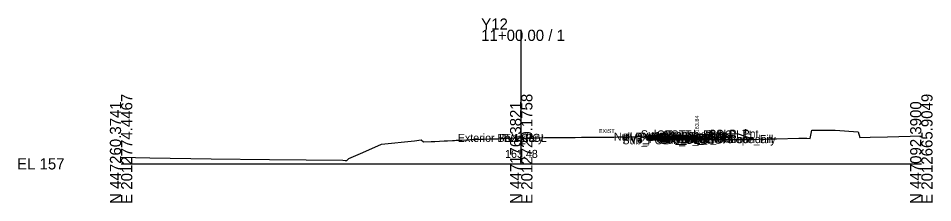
# Model space of a CAD drawing. Extents: x -26 to 1203, y -10 to 9542.
# Drawn here: x -25.7 to 202.8, y 1990.3 to 2036.3 of the extents above; entities that cross this region are included whole.
import ezdxf

# ---------------------------------------------------------------- set-up
doc = ezdxf.new("R2010")
doc.units = 0
for name, color, linetype in [('Default', 7, 'Continuous'), ('Exist Cross Section Cell', 7, 'Continuous'), ('Exist XS Center Line Elevation Label', 7, 'Continuous'), ('Exist XS Ground Line', 7, 'Continuous'), ('Prop CMT Conc Surface', 7, 'Continuous'), ('Prop CMT Concrete Structures', 7, 'Continuous'), ('Prop CMT Pvmt Course 1', 7, 'Continuous'), ('Prop CMT Pvmt Course 1 CG', 7, 'Continuous'), ('Prop CMT Pvmt Course 2', 7, 'Continuous'), ('Prop CMT Pvmt Course 3', 7, 'Continuous'), ('Prop CMT Pvmt Surface', 7, 'Continuous'), ('Prop CMT Slope Grass', 7, 'Continuous'), ('Prop CMT Subgrade Earthwork', 7, 'Continuous'), ('Prop XS Earthwork Shape', 7, 'Continuous'), ('Prop XS Hydro Elevations', 7, 'Continuous'), ('Prop XS SE Text', 7, 'Continuous'), ('Prop XS Side Slope Text', 7, 'Continuous'), ('Scratch_Level_0', 7, 'Continuous')]:
    doc.layers.add(name, color=color, linetype=linetype)

msp = doc.modelspace()

# ---------------------------------------------------------------- linework, layer by layer
at = {"layer": 'Exist Cross Section Cell'}
for p, q in [((100, 2000), (100, 2033.47)), ((0, 2000), (100, 2000)), ((100, 2000), (200, 2000))]:
    msp.add_line(p, q, dxfattribs=at)
at = {"layer": 'Exist XS Ground Line'}
msp.add_lwpolyline([(0, 2001.63), (7.18, 2001.5), (22.54, 2001.22), (37.11, 2001.06), (55.38, 2000.92), (56.03, 2000.85), (56.38, 2000.81), (56.88, 2001.31), (60.43, 2002.79), (65.08, 2004.91), (73.35, 2005.77), (75, 2005.97), (75.54, 2005.5), (77.46, 2005.55), (78.38, 2005.59), (80.74, 2005.72), (81.55, 2005.77), (82.8, 2005.83), (83.36, 2005.86), (83.72, 2005.87), (85.17, 2005.94), (86.69, 2006.02), (87.35, 2006.05), (87.97, 2006.07), (88.66, 2006.09), (89.66, 2006.12), (90.57, 2006.15), (91.96, 2006.2), (92.63, 2006.23), (94.18, 2006.28), (95.61, 2006.33), (96.58, 2006.37), (98.26, 2006.45), (98.61, 2006.46), (98.94, 2006.17), (99.54, 2006.47), (100, 2006.48), (100.44, 2006.5), (101.04, 2006.2), (101.37, 2006.47), (101.74, 2006.47), (102.35, 2006.48), (104.57, 2006.52), (105.83, 2006.54), (107.54, 2006.58), (108.68, 2006.6), (110.78, 2006.61), (111.35, 2006.61), (113.49, 2006.61), (115.04, 2006.62), (116.46, 2006.62), (119.04, 2006.64), (119.59, 2006.64), (121.13, 2006.66), (122.39, 2006.67), (123.11, 2006.68), (124.22, 2006.7), (124.93, 2006.71), (125.37, 2006.71), (127.46, 2006.74), (128.34, 2006.75), (128.82, 2006.76), (130.95, 2006.8), (131.48, 2006.79), (133.42, 2006.94), (134, 2007.44), (138.17, 2007.26), (139.33, 2007.22), (142.95, 2006.78), (144.41, 2006.55), (148.38, 2005.87), (149.45, 2005.96), (152.83, 2006.02), (159.34, 2006.19), (162.22, 2006.21), (163.82, 2006.23), (169.37, 2006.37), (171.34, 2006.37), (172.25, 2006.36), (172.65, 2008.39), (174.53, 2008.39), (178.5, 2008.39), (184.25, 2007.98), (184.61, 2006.58), (187.18, 2006.68), (191.57, 2006.77), (200, 2007)], dxfattribs=at)
at = {"layer": 'Prop CMT Conc Surface'}
msp.add_lwpolyline([(141.94, 2006.9), (143.94, 2006.84), (143.95, 2007.34), (144.45, 2007.34)], dxfattribs=at)
at = {"layer": 'Prop CMT Concrete Structures'}
for points in [[(141.94, 2006.9), (143.94, 2006.84), (143.95, 2007.34), (144.45, 2007.34)], [(144.45, 2007.34), (144.44, 2006.34), (141.94, 2006.32)], [(141.94, 2006.32), (141.94, 2006.9)]]:
    msp.add_lwpolyline(points, dxfattribs=at)
at = {"layer": 'Prop CMT Pvmt Course 1'}
for points in [[(131.46, 2006.79), (141.94, 2006.9)], [(131.46, 2006.79), (131.46, 2006.79)], [(131.46, 2006.54), (131.46, 2006.79)], [(141.94, 2006.65), (131.46, 2006.54)], [(141.94, 2006.9), (141.94, 2006.65)], [(100, 2006.48), (100, 2006.48)]]:
    msp.add_lwpolyline(points, dxfattribs=at)
at = {"layer": 'Prop CMT Pvmt Course 1 CG'}
for points in [[(141.94, 2006.32), (144.94, 2006.35), (145.27, 2006.02)], [(141.94, 2005.98), (141.94, 2006.32)], [(145.27, 2006.02), (141.94, 2005.98)]]:
    msp.add_lwpolyline(points, dxfattribs=at)
at = {"layer": 'Prop CMT Pvmt Course 2'}
for points in [[(131.46, 2006.54), (141.94, 2006.65)], [(131.46, 2006.21), (131.46, 2006.54)], [(141.94, 2006.65), (141.94, 2006.32)], [(141.94, 2006.32), (131.46, 2006.21)]]:
    msp.add_lwpolyline(points, dxfattribs=at)
at = {"layer": 'Prop CMT Pvmt Course 3'}
for points in [[(131.46, 2006.21), (141.94, 2006.32)], [(131.46, 2005.88), (131.46, 2006.21)], [(141.94, 2005.98), (131.46, 2005.88)], [(141.94, 2006.32), (141.94, 2005.98)]]:
    msp.add_lwpolyline(points, dxfattribs=at)
at = {"layer": 'Prop CMT Pvmt Surface'}
msp.add_lwpolyline([(131.46, 2006.79), (141.94, 2006.9)], dxfattribs=at)
at = {"layer": 'Prop CMT Slope Grass'}
msp.add_lwpolyline([(144.45, 2007.34), (153.95, 2007.53), (158.06, 2006.16)], dxfattribs=at)
at = {"layer": 'Prop CMT Subgrade Earthwork'}
for points in [[(131.46, 2005.88), (131.46, 2006.79)], [(141.94, 2005.98), (145.27, 2006.02), (146.64, 2007.38)], [(131.46, 2005.88), (141.94, 2005.98)], [(141.94, 2005.98), (131.46, 2005.88)]]:
    msp.add_lwpolyline(points, dxfattribs=at)
at = {"layer": 'Prop XS Earthwork Shape'}
for points in [[(131.46, 2005.88), (131.46, 2006.79), (131.48, 2006.79), (131.5, 2006.79), (141.94, 2006.9), (141.94, 2006.32), (144.44, 2006.34), (144.44, 2006.54), (145.6, 2006.35), (145.27, 2006.02), (141.94, 2005.98)], [(139.33, 2007.22), (141.94, 2006.9), (131.5, 2006.79), (133.42, 2006.94), (134, 2007.44), (138.17, 2007.26)], [(141.94, 2006.32), (141.94, 2006.9), (141.99, 2006.9), (142.95, 2006.78), (144.41, 2006.55), (144.44, 2006.54), (144.44, 2006.34)], [(153.95, 2007.53), (158.06, 2006.16), (152.83, 2006.02), (149.45, 2005.96), (148.38, 2005.87), (145.6, 2006.35), (146.64, 2007.38)]]:
    msp.add_lwpolyline(points, close=True, dxfattribs=at)

# ---------------------------------------------------------------- texts
at = {"layer": 'Default'}
msp.add_text('-', height=0.0001, dxfattribs=at).set_placement((0, 2000))
at = {"layer": 'Exist Cross Section Cell'}
for s, p in [('Y12', (90, 2033.47)), ('11+00.00 / 1', (90, 2030.67)), ('EL 157', (-26, 1998.6))]:
    msp.add_text(s, height=2.8, dxfattribs=at).set_placement(p)
for s, p in [('E 2012774.4467', (2.8, 1990)), ('E 2012720.1758', (102.8, 1990)), ('E 2012665.9049', (202.8, 1990)), ('N 447260.3741', (0, 1990)), ('N 447176.3821', (100, 1990)), ('N 447092.3900', (200, 1990))]:
    msp.add_text(s, height=2.8, rotation=90, dxfattribs=at).set_placement(p)
at = {"layer": 'Exist XS Center Line Elevation Label'}
msp.add_text('163.48', height=2, dxfattribs=at).set_placement((95.96, 2001.48))
at = {"layer": 'Prop XS Hydro Elevations'}
msp.add_text('163.84', height=1, rotation=90, dxfattribs=at).set_placement((144.44, 2007.84))
at = {"layer": 'Prop XS SE Text'}
msp.add_text('EXIST', height=1, rotation=0.5724, dxfattribs=at).set_placement((119.39, 2007.67))
at = {"layer": 'Prop XS Side Slope Text'}
msp.add_text('3:1', height=1, rotation=341.5651, dxfattribs=at).set_placement((155.49, 2007.81))
at = {"layer": 'Scratch_Level_0'}
for s, p in [('Exterior Boundary', (84.14, 2005.48)), ('PV1_PGL', (94.47, 2005.48)), ('EX CL', (95.67, 2005.48)), ('Null Ex EOP', (123.17, 2005.79)), ('Sub_PGL', (125.28, 2004.88)), ('PV2_PGL', (125.37, 2005.54)), ('PV3_PGL', (125.37, 2005.21)), ('PV1', (129.54, 2005.79)), ('Sub_Trench_Out_DLT', (129.9, 2006.38)), ('CG_Top_Face', (133.9, 2006.34)), ('CG1_Shelf_Out', (134.19, 2005.35)), ('CG_Bot_IE', (134.55, 2005.32)), ('Sub_OEOT', (134.72, 2004.98)), ('CG_Top_Gut', (134.87, 2005.84)), ('PV2_OEOT', (134.81, 2005.65)), ('PV3_OEOT', (134.81, 2005.32)), ('CG_Top_BOC', (135.42, 2006.34)), ('CG_Bot_BOC', (135.45, 2005.34)), ('PV1_OEOT', (135.38, 2005.9)), ('Sub_OEOP', (138.08, 2005.02)), ('Exterior Boundary', (142.2, 2005.16)), ('CSLP_Pnt', (146.81, 2006.53)), ('Slope_Fill', (151.27, 2005.16))]:
    msp.add_text(s, height=2, dxfattribs=at).set_placement(p)

doc.saveas('drawing.dxf')
